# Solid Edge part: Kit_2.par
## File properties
Sűrűség: 0,000 kg/m^3
Pontosság: 0,990
Author: ahadarics
Last saved by: psaghy
Revision: 78
Username: ahadarics
Dokumentum tartalom típus: 0
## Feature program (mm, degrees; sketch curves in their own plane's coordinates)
base feature "unnamed BaseFeature 1"
sketch for "Furat_1" plane through (0, 0, 48.5) normal (0, 0, 1) x-axis (0.707107, -0.707107, 0)
  hole centre (0, 62.9325) bore radius 4.188
hole "Furat_1" nominal diameter 10 finite  VBottomAngle = 118 deg
sketch for "unnamed Hole 1" plane through (0, 0, 48.5) normal (0, 0, 1) x-axis (0.707107, -0.707107, 0)
  hole centre (-62.9325, 0) bore radius 4.188
hole "unnamed Hole 1" finite
sketch for "unnamed Hole 2" plane through (0, 0, 48.5) normal (0, 0, 1) x-axis (0.707107, -0.707107, 0)
  hole centre (0, -62.9325) bore radius 4.188
hole "unnamed Hole 2" finite
sketch for "unnamed Hole 3" plane through (0, 0, 48.5) normal (0, 0, 1) x-axis (0.707107, -0.707107, 0)
  hole centre (62.9325, 0) bore radius 4.188
hole "unnamed Hole 3" finite
pattern "unnamed Pattern 1" of "Furat_1", "unnamed Hole 1", "unnamed Hole 2", "unnamed Hole 3"
sketch for "Furat_5" plane through (55, -0.0046, 26.9988) normal (1, 0, 0) x-axis (0, 0, -1)
  hole centre (-3.5012, 7.0046) bore radius 9.3155
hole "Furat_5" nominal diameter 20.955 finite  ThreadDepth = 25 mm
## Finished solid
Body 1: solid body, 559 faces, 1278 edges, 785 vertices, 8 internal voids.
  Faces by surface: cylinder 177, plane 162, cone 67, sphere 54, torus 53, spline 28, swept 18
  Edges by curve: circle 445, curve on surface 410, line 379, spline 40, ellipse 4
Bounding box of the edges (mm; curved faces can reach further): 110.000 x 110.000 x 78.500, from (-55, -55, 8) to (55, 55, 86.5).
Cylindrical faces by radius (mm): R0.3906 x2, R0.436 x1, R0.4566 x1, R0.5319 x1, R0.6854 x2, R0.701 x1, R0.7273 x1, R0.7952 x1, R0.8489 x1, R0.9223 x1, R1 x31, R1.0003 x1, R1.0017 x8, R1.1393 x1, R1.2532 x1, R1.2992 x1, R1.3173 x1, R1.3418 x1, R1.3734 x1, R1.4839 x1, R1.5702 x1, R1.5902 x3, R1.7026 x2, R1.7139 x2, R1.8341 x1, R2 x12, R2.0009 x12, R2.003 x12, R2.0038 x6, R2.0039 x6, R2.1429 x2, R2.1983 x1, R2.95 x1, R4.188 x8, R5 x4, R5.15 x4, R6 x1, R8 x4, R8.15 x4, R8.5 x2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
Conical faces (half-angle, radius in mm at the cone's reference point): 0.0014 deg R1.001 x6, 1 deg R24.75 x6, 1 deg R44 x6, 1.6538 deg R14.25 x1, 3.5477 deg R15.2454 x1, 5.1705 deg R12.9 x1, 8.3742 deg R12.5032 x1, 13.2989 deg R13.6846 x1, 14.7738 deg R13.2787 x1, 15 deg R25.1732 x1, 25.0169 deg R16.81 x1, 30 deg R6.1443 x1, 30 deg R14.8557 x2, 30 deg R15.1443 x1, 30 deg R26.75 x1, 43.4089 deg R46.25 x1, 45 deg R3.75 x1, 45 deg R3.875 x1, 45 deg R5.3 x8, 45 deg R7.85 x8, 45 deg R10.91 x1, 45 deg R12.65 x2, 45 deg R17.85 x1, 47.9357 deg R39.7887 x6, 47.9357 deg R47.75 x3, 59 deg R4.188 x4
Toroidal faces (ring radius, tube radius in mm): R5.3 r0.3 x4, R5.7 r0.3 x1, R7.95 r0.2 x4, R8.65 r0.5 x4, R11.5 r1 x2, R12.8 r0.3 x1, R12.8088 r0.3 x1, R13.9279 r0.25 x1, R14.7464 r0.5 x1, R15.5 r1 x1, R17.3 r0.2 x1, R23 r3 x1, R23.4827 r1 x1, R26.7154 r2 x6, R28 r0.5 x1, R34.8084 r2 x6, R42.0155 r2 x6, R53 r1 x3, R55.4306 r1 x2, R57 r1 x6
Spherical faces by radius (mm): R1 x18, R2 x36
Planar faces by outward normal: +x 21, +y 11, +z 37, -x 1, -y 10, -z 25, oblique 57
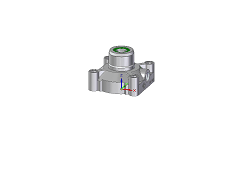
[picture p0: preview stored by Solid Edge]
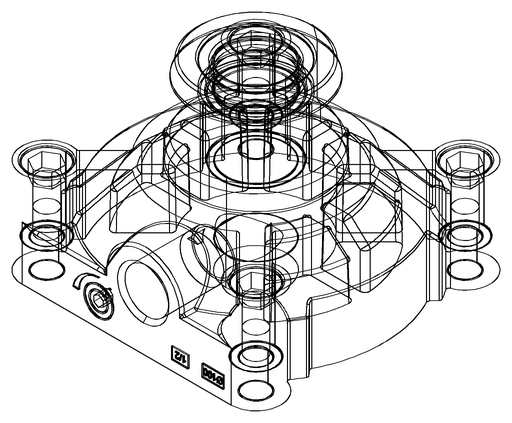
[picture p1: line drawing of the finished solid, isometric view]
